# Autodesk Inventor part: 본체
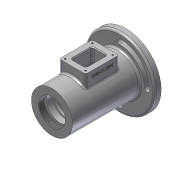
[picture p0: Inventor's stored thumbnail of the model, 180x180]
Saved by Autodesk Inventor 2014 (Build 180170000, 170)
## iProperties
Created: 2017-05
Part Number: 본체
Material: 알루미늄 6061
Document SubType Name: Modeling
Designer: user
Density: 2.71 g/cm^3
Appearance: 알루미늄 - 평지
Mass: 682.471 g
Surface Area: 618.113 cm^2
Volume: 251.834 cm^3
Author: user
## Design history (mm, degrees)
sketch "스케치1"
  geometry: C1 r 31 at (0, 0); 1 further point
  constraints: 1 centre point, 1 coincident
  dimensions: "d1" = 62 diameter of C1
extrude "돌출1" new body sketch "스케치1" distance "d2" = 115; taper "d3" = 0 deg
node "작업 평면1"
sketch "스케치2"
  geometry: C1 r 53 at (0, 0); 1 further point
  constraints: 1 centre point, 1 coincident
  dimensions: "d5" = 106 diameter of C1
extrude "돌출2" join sketch "스케치2" distance "d6" = 10; taper "d7" = 0 deg
node "작업 평면2"
sketch "스케치3"
  geometry: L1 (-31, -115)-(31, -115) reference; L2 (-31, 0)-(31, 0) reference; L3 (0, 0)-(0, -115); L4 (-20, -31)-(20, -31); L5 (20, -31)-(20, -81); L6 (20, -81)-(-20, -81); L7 (-20, -81)-(-20, -31); L8 (-20, -31)-(20, -81); L9 (20, -31)-(-20, -81); 1 further point
  constraints: 14 end point, 3 midpoint, 2 parallel, 1 horizontal, 1 perpendicular, 1 point on line
  dimensions: "d9" = 56 distance from line of L2 point (0, -56); "d10" = 50 distance of L4.end L5.end; "d11" = 40 distance of L4.start L4.end
extrude "돌출3" join sketch "스케치3" stored distance "d12" = 10; taper "d13" = 0 deg
fillet "모깎기1" dims "d14" = 3
fillet "모깎기2" dims "d15" = 3
fillet "모깎기4" dims "d17" = 3
fillet "모깎기5" dims "d18" = 3
sketch "스케치4"
  geometry: L1 (-31, 0)-(31, 0) reference; L2 (-31, -115)-(31, -115) reference; L3 (0, 0)-(0, -115); L4 (0, -9)-(24, -9); L5 (24, -9)-(24, -12); L6 (24, -12)-(0, -12); L7 (0, -12)-(0, -9); L8 (0, -12)-(20, -12); L9 (20, -12)-(20, -21); L10 (20, -21)-(0, -21); L11 (0, -21)-(0, -12); L12 (0, -21)-(17.5, -21); L13 (17.5, -37)-(0, -37); L14 (0, -37)-(0, -21); L15 (0, -24.25)-(18.5, -24.25); L16 (18.5, -24.25)-(18.5, -26); L17 (18.5, -26)-(0, -26); L18 (0, -26)-(0, -24.25); L19 (0, -37)-(26, -37); L20 (26, -37)-(26, -75); L21 (26, -75)-(0, -75); L22 (0, -75)-(0, -37); L23 (0, -75)-(17.5, -75); L24 (17.5, -75)-(17.5, -86); L25 (17.5, -86)-(0, -86); L26 (0, -86)-(0, -75); L27 (0, -86)-(16.5, -86); L28 (16.5, -86)-(16.5, -91); L29 (16.5, -91)-(0, -91); L30 (0, -91)-(0, -86); L31 (0, -91)-(10, -91); L32 (10, -91)-(10, -93.7); L33 (10, -93.7)-(0, -93.7); L34 (0, -93.7)-(0, -91); L35 (0, -93.7)-(12.5, -93.7); L36 (16, -101)-(0, -101); L37 (0, -101)-(0, -93.7); L38 (16, -101)-(22, -115); L39 (22, -115)-(0, -115); L40 (12.5, -93.7)-(12.5, -101); L41 (17.5, -21)-(17.5, -24.25); L42 (17.5, -26)-(17.5, -37); L43 (0, -101)-(0, -115); L44 (0, -101)-(16, -101); L45 (16, -101)-(22, -115); L46 (22, -115)-(0, -115)
  constraints: 88 end point, 19 parallel, 11 perpendicular, 9 horizontal, 6 point on line, 3 collinear, 1 midpoint
  dimensions: "d19" = 3 distance of L4.end L5.end; "d20" = 12 distance between parallel lines of L1 L6; "d21" = 21 distance between parallel lines of L1 L12; "d22" = 26 distance between parallel lines of L1 L17; "d23" = 1.75 distance of L15.end L16.end; "d24" = 11 distance between parallel lines of L19 L17; "d25" = 38 distance of L19.end L20.end; "d27" = 11 distance of L23.end L24.end; "d28" = 5 distance of L27.end L28.end; "d29" = 14 distance between parallel lines of L36 L2; "d31" = 44 diameter of L38.end L3; "d33" = 32 diameter of L36.start L3; "d34" = 7.3 distance of L35.end L40.end; "d35" = 25 diameter of L40 L3; "d36" = 20 diameter of L32 L3; "d37" = 33 diameter of L28 L3; "d38" = 35 diameter of L24 L3; "d39" = 48 diameter of L5 L7; "d40" = 40 diameter of L9 L3; "d41" = 37 diameter of L16 L3; "d43" = 52 diameter of L20 L3; "d44" = 35 diameter of L42 L3; "d45" = 35 diameter of L41 L3
revolve "회전1" sketch "스케치4" stored, may be unused: angle "d46" = 90 deg
sketch "스케치5"
  geometry: C1 r 31 at (0, 0) reference
hole "구멍1" sketch "스케치5" at (0, 0) diameter "d47" = 40.376; stored, may be unused: countersink angle "d51" = 90 deg, drill point angle "d53" = 0 deg; dims "d48" = 10, "d49" = 4, "d50" = 2, "d52" = 11
sketch "스케치6"
  geometry: L1 (-17, 81)-(17, 81) reference; L2 (-20, 34)-(-20, 78) reference; L3 (17, 31)-(-17, 31) reference; L4 (20, 78)-(20, 34) reference; L5 (-20, 56)-(20, 56); L6 (0, 31)-(0, 81); L7 (11, 40)-(-11, 40); L8 (-11, 40)-(-11, 72); L9 (-11, 72)-(11, 72); L10 (11, 72)-(11, 40); L11 (11, 40)-(-11, 72); L12 (-11, 40)-(11, 72); 2 further points
  constraints: 16 end point, 7 midpoint, 2 parallel, 1 horizontal, 1 perpendicular
  dimensions: "d54" = 32 distance of L7.end L8.end; "d55" = 22 distance of L8.end L9.end
extrude "돌출4" cut sketch "스케치6" distance "d56" = 39.5; taper "d57" = 0 deg
fillet "모깎기6" dims "d58" = 3
fillet "모깎기8" dims "d60" = 3
fillet "모깎기9" dims "d61" = 0.3
chamfer "모따기1" distance "d62" = 0.7; stored, may be unused: second distance "d63" = 2, angle "d64" = 30 deg
fillet "모깎기10" dims "d65" = 3
fillet "모깎기11" dims "d66" = 0.3
chamfer "모따기2" distance "d67" = 1; stored, may be unused: second distance "d68" = 2, angle "d69" = 30 deg
chamfer "모따기3" distance "d70" = 1; stored, may be unused: second distance "d71" = 2, angle "d72" = 30 deg
fillet "모깎기12" dims "d76" = 3
chamfer "모따기5" distance "d77" = 1; stored, may be unused: second distance "d78" = 2, angle "d79" = 30 deg
sketch "스케치8"
  geometry: L1 (-17, 81)-(17, 81) reference; L2 (-20, 34)-(-20, 78) reference; L3 (17, 31)-(-17, 31) reference; L4 (20, 78)-(20, 34) reference; L5 (-20, 56)-(20, 56); L6 (0, 31)-(0, 81); L7 (15.5, 35.5)-(-15.5, 35.5); L8 (-15.5, 35.5)-(-15.5, 76.5); L9 (-15.5, 76.5)-(15.5, 76.5); L10 (15.5, 76.5)-(15.5, 35.5); L11 (15.5, 35.5)-(-15.5, 76.5); L12 (-15.5, 35.5)-(15.5, 76.5); 2 further points
  constraints: 16 end point, 7 midpoint, 2 parallel, 1 horizontal, 1 perpendicular
  dimensions: "d80" = 41 distance of L7.end L8.end; "d81" = 31 distance of L7.start L7.end
hole "구멍2" sketch "스케치8" at (-15.5, 35.5), (-15.5, 76.5), (15.5, 76.5), (15.5, 35.5) diameter "d82" = 2.459; stored, may be unused: countersink angle "d86" = 90 deg, drill point angle "d88" = 118 deg; dims "d83" = 6, "d84" = 4, "d85" = 2, "d87" = 8
sketch "스케치9"
  geometry: L1 (0, 45.5)-(0, -45.5); L2 (-45.5, 0)-(45.5, 0); C1 r 31 at (0, 0) reference; A1 r 41.5 centre (0, 0) between (0, 41.5) and (-41.5, 0); A2 r 4 centre (0, 41.5) between (0, 37.5) and (0, 45.5); A3 r 4 centre (-41.5, 0) between (-45.5, 0) and (-37.5, 0); A4 r 4 centre (41.5, 0) between (45.5, 0) and (37.5, 0); A5 r 4 centre (0, -41.5) between (0, -37.5) and (0, -45.5); A6 r 37.5 centre (0, 0) between (0, 37.5) and (-37.5, 0); A7 r 37.5 centre (0, 0) between (0, -37.5) and (37.5, 0); A8 r 45.5 centre (0, 0) between (0, 45.5) and (-45.5, 0); A9 r 45.5 centre (0, 0) between (0, -45.5) and (45.5, 0)
  constraints: 20 point on circle, 9 centre point, 6 point on line, 4 end point, 3 coincident, 1 perpendicular, 1 vertical
  dimensions: "d89" = 83 diameter of A1; "d92" = 37.5 radius of A6; "d93" = 37.5 radius of A7; "d94" = 45.5 radius of A9; "d95" = 4 radius of A5
extrude "돌출5" cut sketch "스케치9" stored distance "d96" = 10; taper "d97" = 0 deg
node "작업 평면3"
sketch "스케치10"
  geometry: L1 (-34, -75)-(-34, -13) reference; L2 (44, 0)-(0, 0) reference; 2 further points
  constraints: 1 other
  dimensions: "d99" = 56 horizontal distance of point (22, -8) L1.end; "d100" = 8 distance from line of point (22, -8) L2
feature "엠보싱1" sketch "스케치10" dims "d3" = 0, "d12" = 10, "d13" = 0, "d101" = 0.5, "d102" = 0
node "솔리드1"
other parameters: "d4" = -3, "d8" = 44, "d42" = 35, "d90" = 75, "d91" = 91, "d98" = 33.25
